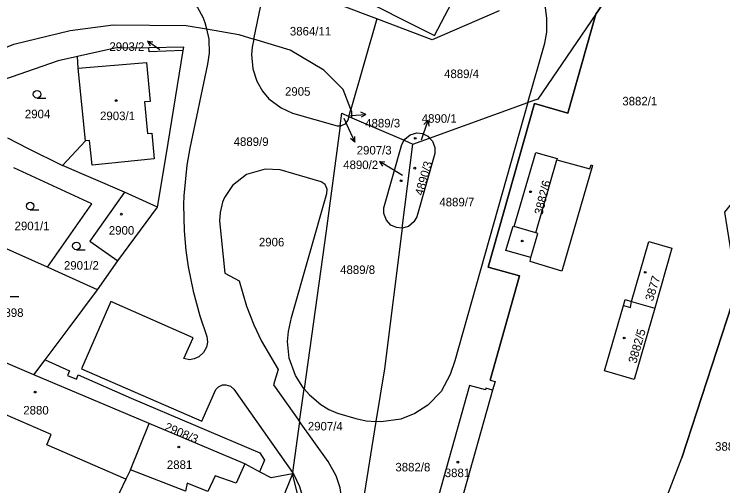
# Model space of a CAD drawing. Extents: x -527335 to -526256, y -1079142 to -1077809.
# Drawn here: x -526891.4 to -526750.4, y -1078714.2 to -1078620.2 of the extents above; entities that cross this region are included whole.
import ezdxf

# ---------------------------------------------------------------- set-up
doc = ezdxf.new("R2010")
doc.units = 0
for name, color, linetype in [('Vrstva 1', 7, 'Continuous'), ('Vrstva 2', 7, 'Continuous'), ('Vrstva 3', 7, 'Continuous'), ('Vrstva 4', 7, 'Continuous'), ('Vrstva 5', 7, 'Continuous'), ('Vrstva 54', 7, 'Continuous'), ('Vrstva 7', 7, 'Continuous')]:
    doc.layers.add(name, color=color, linetype=linetype)

msp = doc.modelspace()

# ---------------------------------------------------------------- linework, layer by layer
at = {"layer": 'Vrstva 1'}
for p, q in [((-526843.73, -1078625.21), (-526841.41, -1078613.96)), ((-526819.27, -1078621.16), (-526824.4, -1078639.2)), ((-526808.76, -1078644.91), (-526789.19, -1078637.84)), ((-526824.79, -1078640.59), (-526824.4, -1078639.2)), ((-526824.79, -1078640.59), (-526824.19, -1078640.85)), ((-526824.19, -1078640.85), (-526813.82, -1078645.35)), ((-526814.2, -1078662.85), (-526812.08, -1078646.11)), ((-526813.82, -1078645.35), (-526812.08, -1078646.11)), ((-526812.08, -1078646.11), (-526808.76, -1078644.91)), ((-526869.47, -1078655.69), (-526881.81, -1078650.35)), ((-526862.92, -1078658.65), (-526869.47, -1078655.69)), ((-526870.77, -1078669.37), (-526862.92, -1078658.65)), ((-526884.81, -1078670.65), (-526900.22, -1078663.69)), ((-526874.82, -1078675.16), (-526870.77, -1078669.37)), ((-526768.55, -1078677.49), (-526763.94, -1078678.83)), ((-526887.47, -1078692.06), (-526885.27, -1078689.12)), ((-526864.56, -1078701.77), (-526887.47, -1078692.06)), ((-526834.61, -1078701.38), (-526833.7, -1078694.84)), ((-526796.21, -1078695.13), (-526804.6, -1078724.76)), ((-526868.26, -1078711.02), (-526864.56, -1078701.77)), ((-526845.53, -1078709.84), (-526864.56, -1078701.77)), ((-526834.61, -1078701.38), (-526836.01, -1078711.53)), ((-526819.43, -1078701.36), (-526822.95, -1078723.3)), ((-526842.59, -1078711.4), (-526845.53, -1078709.84)), ((-526836.05, -1078711.79), (-526839.19, -1078719.76)), ((-526836.01, -1078711.53), (-526836.05, -1078711.79)), ((-526833.99, -1078719.88), (-526836.05, -1078711.79))]:
    msp.add_line(p, q, dxfattribs=at)
for points in [[(-526766.12, -1078610.17), (-526769.16, -1078610.73), (-526775.66, -1078620.23)], [(-526869.37, -1078612.14), (-526867.13, -1078612.03), (-526863.95, -1078612.46), (-526860.92, -1078613.57), (-526858.13, -1078615.36), (-526857.06, -1078616.32), (-526854.94, -1078618.9), (-526853.89, -1078620.81), (-526853.48, -1078621.91), (-526853.17, -1078623.18)], [(-526789.19, -1078637.84), (-526785.84, -1078625.99), (-526785.42, -1078623.83), (-526785.41, -1078621.01), (-526785.67, -1078618.95), (-526786.3, -1078616.83), (-526788.13, -1078613.38), (-526789.05, -1078612.35)], [(-526819.27, -1078621.16), (-526833.71, -1078615.66), (-526841.41, -1078613.96)], [(-526824.79, -1078615.85), (-526807.79, -1078624.46), (-526803.66, -1078616.58)], [(-526794.91, -1078619.55), (-526808.25, -1078625.35), (-526819.27, -1078621.16)], [(-526775.66, -1078620.23), (-526781.26, -1078639.92), (-526787.88, -1078638.05), (-526797.07, -1078670.6), (-526790.82, -1078672.37), (-526796.68, -1078693.11), (-526795.72, -1078693.38), (-526796.21, -1078695.13)], [(-526775.66, -1078620.23), (-526787.22, -1078637.13), (-526789.19, -1078637.84)], [(-526921.59, -1078644.68), (-526904.95, -1078631.71), (-526891.51, -1078626.22), (-526880.24, -1078623.51), (-526871.73, -1078622.35), (-526857.21, -1078622.49), (-526853.17, -1078623.18)], [(-526853.17, -1078623.18), (-526852.68, -1078625.23), (-526852.63, -1078628.02), (-526852.92, -1078630.22), (-526856.44, -1078646.89), (-526857.06, -1078650.28), (-526857.65, -1078656.43), (-526857.7, -1078658.13), (-526857.58, -1078663.37), (-526857.25, -1078667.34), (-526856.78, -1078670.59), (-526855.82, -1078675.44), (-526854.48, -1078680.3), (-526853.09, -1078684.47), (-526852.97, -1078685.55), (-526853.14, -1078686.59), (-526853.72, -1078687.66), (-526854.66, -1078688.48), (-526855.62, -1078688.92), (-526856.53, -1078689.06), (-526857.64, -1078688.84), (-526855.82, -1078684.74), (-526872.17, -1078677.46), (-526878.01, -1078690.91), (-526854.06, -1078701.28), (-526851.27, -1078695), (-526850.77, -1078694.45), (-526849.95, -1078694.09), (-526849.31, -1078694.04), (-526848.37, -1078694.36), (-526847.72, -1078694.95), (-526836.01, -1078711.53)], [(-526853.17, -1078623.18), (-526846.72, -1078624.29), (-526843.73, -1078625.21)], [(-526843.73, -1078625.21), (-526844.05, -1078626.78), (-526844.2, -1078628.27), (-526843.91, -1078631.11), (-526843.13, -1078633.56), (-526842.02, -1078635.55), (-526840.76, -1078637.11), (-526838.3, -1078638.92), (-526836.02, -1078639.96), (-526827.16, -1078642.46), (-526826.53, -1078642.46)], [(-526824.4, -1078639.2), (-526825.96, -1078635.22), (-526829.78, -1078631.37), (-526836.5, -1078627.43), (-526843.73, -1078625.21)], [(-526864.61, -1078626.91), (-526871.37, -1078627.02), (-526878.81, -1078628.66)], [(-526857.75, -1078627.47), (-526857.64, -1078626.79), (-526864.61, -1078626.91)], [(-526857.75, -1078627.47), (-526864.55, -1078627.7), (-526864.61, -1078626.91)], [(-526862.92, -1078658.65), (-526861.14, -1078648.4), (-526857.75, -1078627.47)], [(-526878.81, -1078628.66), (-526882.67, -1078629.51), (-526901.46, -1078636.01), (-526901.58, -1078636.57)], [(-526881.81, -1078650.35), (-526877.21, -1078645.49), (-526878.67, -1078630.96), (-526878.81, -1078628.66)], [(-526789.19, -1078637.84), (-526803.74, -1078689.27), (-526804.63, -1078692.01), (-526806.42, -1078695.38), (-526809.08, -1078698.09), (-526811.68, -1078699.8), (-526814.45, -1078700.92), (-526818.39, -1078701.44), (-526819.43, -1078701.36)], [(-526826.53, -1078642.46), (-526826.2, -1078639.98), (-526824.79, -1078640.59)], [(-526824.19, -1078640.85), (-526824.2, -1078639.7), (-526824.4, -1078639.2)], [(-526824.79, -1078640.59), (-526825, -1078641.33), (-526825.59, -1078642.15), (-526826.34, -1078642.46), (-526826.53, -1078642.46)], [(-526826.53, -1078642.46), (-526829.34, -1078663.37), (-526833.7, -1078694.84)], [(-526813.82, -1078645.35), (-526813.7, -1078645.14), (-526812.63, -1078644.28), (-526811.27, -1078643.9), (-526810.18, -1078644.02), (-526809.12, -1078644.53), (-526808.76, -1078644.91)], [(-526892.72, -1078644.86), (-526888.78, -1078646.91), (-526881.81, -1078650.35)], [(-526814.2, -1078662.85), (-526815.36, -1078662.74), (-526816.43, -1078662.24), (-526817.34, -1078661.29), (-526817.86, -1078659.97), (-526817.84, -1078658.8), (-526814.29, -1078646.19), (-526813.82, -1078645.35)], [(-526808.76, -1078644.91), (-526808.17, -1078645.52), (-526807.69, -1078646.82), (-526807.7, -1078648.01), (-526811.28, -1078660.61), (-526811.85, -1078661.63), (-526812.94, -1078662.52), (-526814.17, -1078662.85), (-526814.2, -1078662.85)], [(-526788.7, -1078669.48), (-526788.59, -1078668.73), (-526793.57, -1078667.29), (-526792.14, -1078662.45), (-526791.9, -1078662.52), (-526787.63, -1078647.77), (-526783.36, -1078648.99), (-526783.43, -1078649.22), (-526776.87, -1078651.04), (-526776.62, -1078650.25), (-526776.3, -1078650.36), (-526782.4, -1078671.44), (-526788.7, -1078669.48)], [(-526884.81, -1078670.65), (-526875.97, -1078658.01), (-526891.48, -1078650.84)], [(-526833.7, -1078694.84), (-526833.97, -1078694.53), (-526835.42, -1078692.18), (-526836.66, -1078688.74), (-526837.04, -1078685.43), (-526836.83, -1078683.47), (-526836.21, -1078680.65), (-526829.17, -1078655.93), (-526829.11, -1078655.11), (-526829.53, -1078654.17), (-526830.32, -1078653.6), (-526838.47, -1078651.25), (-526841.47, -1078651.1), (-526845.15, -1078652.19), (-526847.97, -1078654.37), (-526849.57, -1078656.72), (-526849.98, -1078657.67), (-526850.44, -1078659.71), (-526850.52, -1078661.43), (-526849.51, -1078671.82), (-526846.64, -1078673.34), (-526845.17, -1078678.38), (-526843.73, -1078682.14), (-526842.22, -1078685.38), (-526838.87, -1078691.04), (-526839.82, -1078694.07), (-526834.61, -1078701.38)], [(-526869.47, -1078655.69), (-526876.34, -1078665.47), (-526870.77, -1078669.37)], [(-526814.2, -1078662.85), (-526817.74, -1078690.87), (-526819.43, -1078701.36)], [(-526768.55, -1078677.49), (-526765.14, -1078665.52), (-526760.53, -1078666.85), (-526763.94, -1078678.83)], [(-526874.82, -1078675.16), (-526881.1, -1078672.32), (-526884.81, -1078670.65)], [(-526885.27, -1078689.12), (-526880.66, -1078682.97), (-526874.82, -1078675.16)], [(-526766.02, -1078728.13), (-526758.54, -1078708.63), (-526747.6, -1078675.03)], [(-526763.94, -1078678.83), (-526768.04, -1078693.02), (-526773.94, -1078691.29), (-526770.16, -1078678.27), (-526769.81, -1078677.09), (-526768.55, -1078677.49)], [(-526887.47, -1078692.06), (-526904.29, -1078684.93), (-526904.54, -1078685.32), (-526910.1, -1078683.31)], [(-526885.27, -1078689.12), (-526880.41, -1078691.26), (-526880.83, -1078692.23), (-526879.04, -1078692.97), (-526878.66, -1078692.08), (-526868.1, -1078696.74), (-526842.55, -1078707.6), (-526841.58, -1078709.05), (-526842.59, -1078711.4)], [(-526833.7, -1078694.84), (-526832.67, -1078696.05), (-526830.4, -1078698.02), (-526828.77, -1078698.97), (-526827.06, -1078699.72), (-526823.43, -1078700.8), (-526821.39, -1078701.21), (-526819.43, -1078701.36)], [(-526796.21, -1078695.13), (-526797.53, -1078694.71), (-526797.63, -1078695.06), (-526800.78, -1078694.21), (-526809.06, -1078723.54), (-526804.6, -1078724.76)], [(-526822.95, -1078723.3), (-526827.09, -1078722.05), (-526826.54, -1078720.12), (-526826.24, -1078716.92), (-526826.57, -1078714.61), (-526827.31, -1078712.18), (-526828.95, -1078709.32), (-526834.61, -1078701.38)], [(-526845.53, -1078709.84), (-526847.23, -1078713.67), (-526851.39, -1078712.19), (-526852.86, -1078715.34), (-526856.99, -1078713.69), (-526857.33, -1078715.27), (-526868.26, -1078711.02)], [(-526868.26, -1078711.02), (-526869.17, -1078712.87), (-526874.21, -1078723.48)], [(-526836.05, -1078711.79), (-526840.28, -1078712.62), (-526842.59, -1078711.4)], [(-526836.01, -1078711.53), (-526835.83, -1078711.79), (-526834.6, -1078714.3), (-526833.95, -1078716.6), (-526833.92, -1078719.44)]]:
    msp.add_lwpolyline(points, dxfattribs=at)
at = {"layer": 'Vrstva 3'}
for p, q in [((-526886.86, -1078636.93), (-526885.11, -1078636.93)), ((-526888.23, -1078659.2), (-526886.48, -1078659.2)), ((-526879.03, -1078667.16), (-526877.28, -1078667.16)), ((-526892.21, -1078676.49), (-526890.46, -1078676.49))]:
    msp.add_line(p, q, dxfattribs=at)
for centre in [(-526886.86, -1078636.18), (-526888.23, -1078658.45), (-526879.03, -1078666.41)]:
    msp.add_circle(centre, 0.75, dxfattribs=at)
at = {"layer": 'Vrstva 4'}
for p, q in [((-526878.67, -1078630.96), (-526865.05, -1078629.86)), ((-526865.05, -1078629.86), (-526864.34, -1078637.6)), ((-526864.34, -1078637.6), (-526865.46, -1078637.7)), ((-526865.46, -1078637.7), (-526864.89, -1078644.02)), ((-526864.89, -1078644.02), (-526863.99, -1078643.94)), ((-526863.99, -1078643.94), (-526863.53, -1078649.08)), ((-526876.39, -1078645.4), (-526877.21, -1078645.49)), ((-526875.9, -1078650.32), (-526876.39, -1078645.4)), ((-526863.53, -1078649.08), (-526875.9, -1078650.32)), ((-526787.62, -1078663.77), (-526783.43, -1078649.22)), ((-526787.62, -1078663.77), (-526791.9, -1078662.52)), ((-526788.59, -1078668.73), (-526787.18, -1078663.9)), ((-526787.18, -1078663.9), (-526787.62, -1078663.77)), ((-526770.16, -1078678.27), (-526768.76, -1078678.67)), ((-526768.76, -1078678.67), (-526768.55, -1078677.49)), ((-526884.03, -1078703.98), (-526913.74, -1078691.1)), ((-526884.91, -1078706.03), (-526884.03, -1078703.98)), ((-526869.17, -1078712.87), (-526884.91, -1078706.03))]:
    msp.add_line(p, q, dxfattribs=at)
at = {"layer": 'Vrstva 5'}
for centre in [(-526871.11, -1078637.45), (-526811.59, -1078644.96), (-526811.69, -1078650.91), (-526814.42, -1078653.41), (-526788.64, -1078655.61), (-526870.09, -1078660.07), (-526790.31, -1078665.42), (-526765.83, -1078671.65), (-526770.01, -1078684.75), (-526887.25, -1078695.52), (-526858.66, -1078706.46), (-526803.1, -1078709.48)]:
    msp.add_circle(centre, 0.175, dxfattribs=at)
at = {"layer": 'Vrstva 54'}
for points in [[(-526796.68, -1078693.11), (-526790.82, -1078672.37), (-526797.07, -1078670.6), (-526787.88, -1078638.05), (-526781.26, -1078639.92), (-526775.66, -1078620.23), (-526769.16, -1078610.73), (-526766.12, -1078610.17)], [(-526747.97, -1078618.86), (-526745.47, -1078625.12), (-526744.86, -1078629.16), (-526744.86, -1078637), (-526748.33, -1078652.79), (-526747.95, -1078657.02), (-526750.05, -1078659.68), (-526747.6, -1078675.03), (-526758.54, -1078708.63)]]:
    msp.add_lwpolyline(points, dxfattribs=at)
at = {"layer": 'Vrstva 7'}
for p, q in [((-526862.45, -1078627.3), (-526864.91, -1078625.58)), ((-526864.91, -1078625.58), (-526863.8, -1078625.74)), ((-526864.91, -1078625.58), (-526864.38, -1078626.56)), ((-526824.46, -1078640.41), (-526824.4, -1078640.4)), ((-526824.4, -1078640.4), (-526821.41, -1078640.19)), ((-526821.41, -1078640.19), (-526822.44, -1078639.76)), ((-526821.41, -1078640.19), (-526822.37, -1078640.76)), ((-526825.84, -1078640.96), (-526824.9, -1078642.99)), ((-526810.04, -1078644.24), (-526809.06, -1078641.4)), ((-526809.06, -1078641.4), (-526809.86, -1078642.19)), ((-526809.06, -1078641.4), (-526808.92, -1078642.51)), ((-526824.9, -1078642.99), (-526823.63, -1078645.71)), ((-526823.63, -1078645.71), (-526823.6, -1078644.59)), ((-526810.38, -1078645.23), (-526810.04, -1078644.24)), ((-526823.63, -1078645.71), (-526824.51, -1078645.01)), ((-526816.17, -1078651.13), (-526818.74, -1078649.58)), ((-526818.74, -1078649.58), (-526817.63, -1078649.67)), ((-526818.74, -1078649.58), (-526818.14, -1078650.53)), ((-526814.14, -1078652.37), (-526816.17, -1078651.13))]:
    msp.add_line(p, q, dxfattribs=at)

# ---------------------------------------------------------------- texts
at = {"layer": 'Vrstva 2'}
for s, p in [('3864/11', (-526836.55, -1078624.47)), ('2903/2', (-526872.46, -1078627.54)), ('4889/4', (-526805.86, -1078632.96)), ('2905', (-526837.52, -1078636.48)), ('3882/1', (-526770.39, -1078638.4)), ('2904', (-526889.28, -1078640.96)), ('2903/1', (-526874.32, -1078641.34)), ('4890/1', (-526810.31, -1078641.86)), ('4889/3', (-526821.56, -1078642.79)), ('4889/9', (-526847.74, -1078646.48)), ('2907/3', (-526823.25, -1078648.18)), ('4890/2', (-526825.93, -1078651.09)), ('4889/7', (-526806.8, -1078658.51)), ('2901/1', (-526891.33, -1078663.26)), ('2900', (-526872.57, -1078664.15)), ('2906', (-526842.71, -1078666.49)), ('2901/2', (-526881.51, -1078671.13)), ('4889/8', (-526826.54, -1078671.99)), ('2898', (-526894.61, -1078680.54)), ('2880', (-526889.6, -1078699.98)), ('2907/4', (-526832.97, -1078703.16)), ('3882/7', (-526751.93, -1078707.2)), ('2881', (-526861.02, -1078710.83)), ('3882/8', (-526815.55, -1078711.32)), ('3881', (-526805.73, -1078712.46))]:
    msp.add_text(s, height=1.7, dxfattribs=at).set_placement(p)
for s, rotation, p in [('4890/3', 74, (-526810.09, -1078656.5)), ('3882/6', 76, (-526786.29, -1078660.33)), ('3877', 73, (-526764.29, -1078677.52)), ('3882/5', 74, (-526767.62, -1078689.92)), ('2908/3', 337, (-526861.64, -1078703.07))]:
    msp.add_text(s, height=1.7, rotation=rotation, dxfattribs=at).set_placement(p)

doc.saveas('drawing.dxf')
